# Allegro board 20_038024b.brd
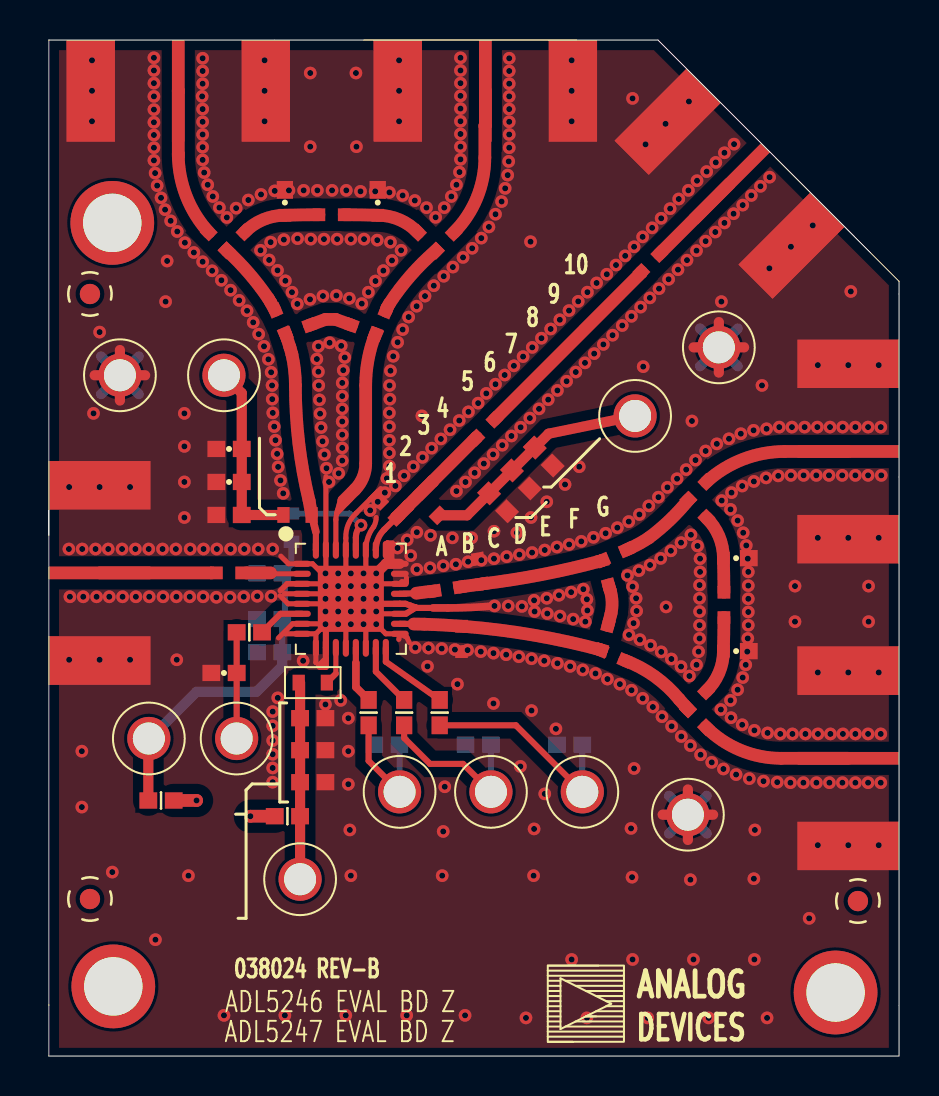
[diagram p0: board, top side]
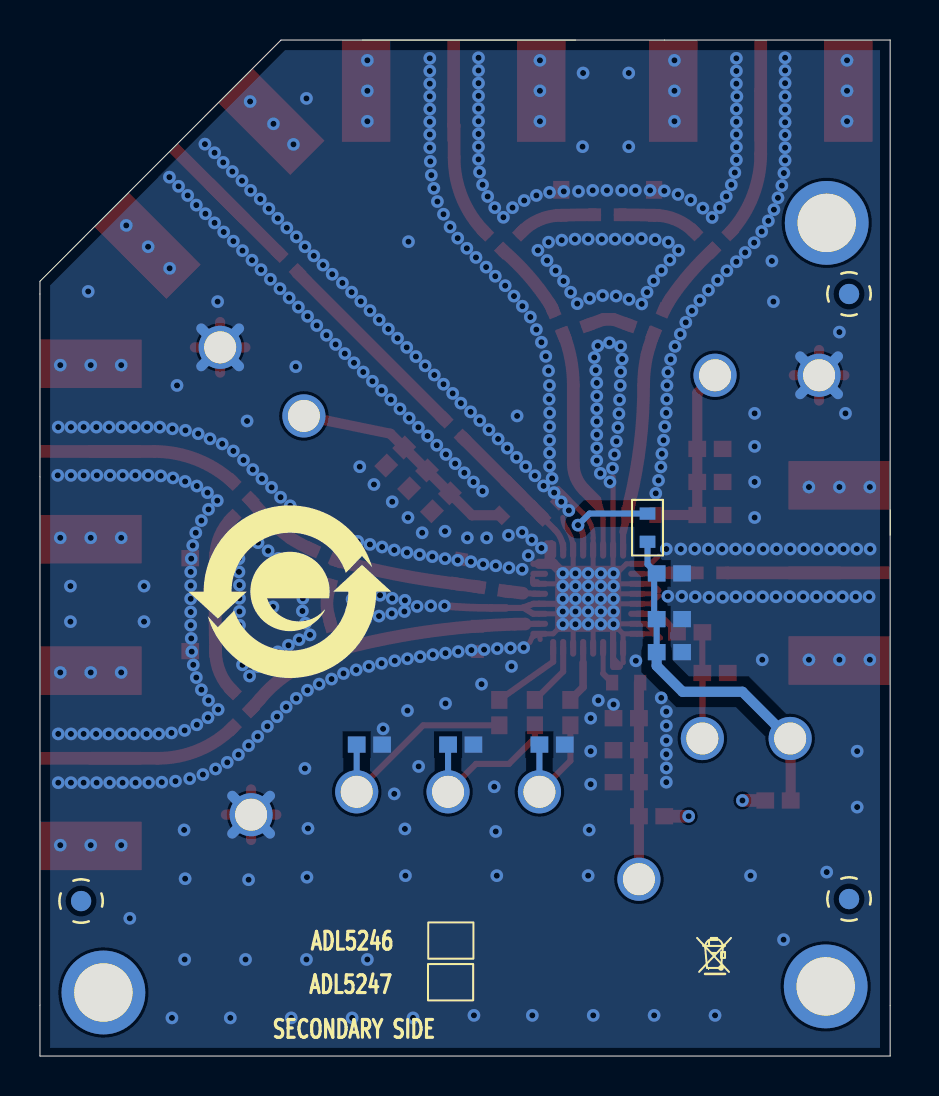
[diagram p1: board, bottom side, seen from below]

Outline 42.55 x 50.8 mm; copper layers: TOP, L2_GND, L3_VCC, BOTTOM. Coordinates in mm from the lower left corner of the outline.
Outline path: 0,27.3 0,0 42.55,0 42.55,38.73 30.48,50.8 15.75,50.8 ; 0,26.04 0,50.8 26.42,50.8

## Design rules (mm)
nets with their own width: min track width 0.508; nets AGND

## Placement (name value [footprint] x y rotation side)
C1  2.7pF  [C0402]  16.94 27.36 135 top
C2  0.1UF  [C0402]  13.21 13.69 180 top
C3  1.5pF  [C0402]  19.93 23.35 8.9 top
C4  1000pF  [C0402]  13.21 15.29 0 top
C5  100pF  [C0402]  9.02 27.05 180 top
C6  100pF  [C0402]  8.76 19.15 180 top
C7  100pF  [C0402]  13.21 16.89 0 top
C8  100pF  [C0402]  9.02 24.16 0 top
C9  100pF  [C0402]  8.45 40.73 315 top
C10  100pF  [C0402]  9.34 40.73 45 top
C11  100pF  [C0402]  16.92 15.57 180 bottom
C12  100pF  [C0402]  18.92 40.72 315 top
C13  100pF  [C0402]  19.81 40.72 225 top
C14  100pF  [C0402]  21.49 15.57 180 bottom
C15  100pF  [C0402]  26.06 15.57 180 bottom
C16  100pF  [C0402]  11.05 24.13 180 bottom
C17  1000pF  [C0402]  11.05 21.84 180 bottom
C18  100pF  [C0402]  32.45 27.36 315 top
C19  100pF  [C0402]  32.44 17.78 225 top
C20  0.1UF  [C0402]  11.05 20.19 0 bottom
C21  100pF  [C0402]  32.45 28.25 225 top
C22  100pF  [C0402]  32.44 16.89 135 top
C23  100pF  [C0402]  30.1 39.65 225 top
C24  100pF  [C0402]  22.48 27.69 315 top
C25  1000pF  [C0402]  23.62 28.83 315 top
C26  0.1UF  [C0402]  24.77 29.97 135 top
C27  100pF  [C0402]  12.45 36.32 200 top
C28  100pF  [C0402]  15.75 36.32 160 top
C29  100pF  [C0402]  27.85 24.16 285 top
C30  100pF  [C0402]  27.82 20.91 255 top
C31  100pF  [C0402]  34.39 24.89 0 top
C32  100pF  [C0402]  34.39 20.24 0 top
C33  100pF  [C0402]  11.81 42.67 90 top
C34  100pF  [C0402]  16.46 42.67 90 top
C40  0.1UF  [C0402]  9.02 30.35 0 top
C41  1000pF  [C0402]  9.02 28.7 180 top
GND1  BLK  [CNLOOPTP]  3.56 34.04 0 top
GND2  BLK  [CNLOOPTP]  33.53 35.43 0 top
GND3  BLK  [CNLOOPTP]  31.98 12.06 0 top
L1  100nH  [L7144]  12.45 27.05 0 top
L2  10NH  [L7144]  13.21 18.67 0 top
L3  100nH  [L7144]  12.14 26.42 270 bottom
L4  100nH  [L7144]  19 27.53 315 top
L5  TBD0402  [L0402]  20.65 20.85 270 top
L6  1nH  [L0402]  21.59 24.23 280 top
L7  TBD0402  [L0402]  33.78 22.56 270 top
L8  TBD0402  [L0402]  14.15 42.06 0 top
NOREF  -  [unnamed]  40.49 7.75 0 top
NOREF#2  -  [#2]  144.15 241.3 0 top
NOREF#3  -  [#2]  0 50.8 0 top
NOREF#4  -  [#2]  -121.16 -134.37 0 top
NOREF#5  -  [#2]  -155.57 170.18 0 top
NOREF#6  -  [#2]  149.86 63.5 180 top
NOREF#7  -  [#2]  167.16 -14.48 0 top
NOREF#8  -  [#2]  41.53 0 90 top
NOREF#9  -  [unnamed]  2.06 7.85 0 top
NOREF#10  -  [#2]  39.37 3.18 0 top
NOREF#11  -  [#2]  -240.23 -69.11 0 top
NOREF#12  -  [#2]  -155.57 200.66 0 top
NOREF#13  -  [#2]  24.97 0.71 0 top
NOREF#14  -  [unnamed]  2.06 38.1 0 top
NOREF#15  -  [#2]  0 0 0 top
NOREF#16  -  [#2]  -292.74 -238.76 0 top
NOREF#17  -  [#2]  -47.37 68.58 0 top
NOREF#18  -  [#2]  0 50.8 0 top
NOREF#19  -  [#2]  39.37 3.18 0 top
NOREF#20  -  [#2]  -237.72 -119 0 top
NOREF#21  -  [#2]  42.55 0 90 top
NOREF#22  -  [#2]  149.86 -15.24 90 top
NOREF#23  -  [#2]  39.37 3.18 0 top
NOREF#24  -  [#2]  0 63.53 270 top
NOREF#25  -  [#2]  0 -15.24 0 top
NOREF#26  -  [unnamed]  2.06 38.1 180 bottom
NOREF#27  -  [unnamed]  3.18 41.66 180 bottom
NOREF#28  -  [unnamed]  2.06 7.85 180 bottom
NOREF#29  -  [unnamed]  40.49 7.75 180 bottom
NOREF#30  -  [unnamed]  39.37 3.18 180 bottom
NOREF#31  -  [#2]  30.04 23.22 180 bottom
NOREF#32  -  [#2]  8.76 5 180 bottom
NOREF#33  -  [unnamed]  3.23 3.48 180 bottom
R1  0  [R0402]  21.84 31.37 45 top
R2  100  [R0402]  10.03 21.18 0 top
R3  100  [R0402]  16 17.17 270 top
R4  100  [R0402]  17.78 17.17 270 top
R5  100  [R0402]  19.56 17.17 270 top
R6  0  [R0402]  11.94 11.99 0 top
R7  0  [R0402]  5.61 12.78 0 top
R8  0  [R0402]  11.57 36.7 113.5 top
R9  0  [R0402]  16.61 36.66 66.5 top
R10  0  [R0402]  28.31 25.05 23.5 top
R11  0  [R0402]  28.23 20.03 337 top
RFIN1  JOHNSON142-0701-851  [CNJOHNSON142-0701-851]  2.54 24.16 180 top
RFIN2  JOHNSON142-0701-851  [CNJOHNSON142-0701-851]  21.84 48.26 90 top
RFIN3  JOHNSON142-0701-851  [CNJOHNSON142-0701-851]  40 30.23 0 top
RFOUT1  JOHNSON142-0701-851  [CNJOHNSON142-0701-851]  6.48 48.26 90 top
RFOUT2  JOHNSON142-0701-851  [CNJOHNSON142-0701-851]  40 14.88 0 top
RFOUT3  JOHNSON142-0701-851  [CNJOHNSON142-0701-851]  34.06 43.61 45 top
U1  ADL5246ACPZN  [QFN32_5X5_PAD3_3X3_3]  15.11 22.86 270 top
VCC1  RED  [CNLOOPTP]  8.76 34.04 0 top
VCC2  RED  [CNLOOPTP]  29.34 32 0 top
VGAIN1  YEL  [CNLOOPTP]  22.12 13.21 0 top
VGAIN2  YEL  [CNLOOPTP]  26.7 13.21 0 top
VPOS1  RED  [CNLOOPTP]  12.57 8.84 0 top
VPOS2  RED  [CNLOOPTP]  5 15.88 0 top
VSW1  YEL  [CNLOOPTP]  17.55 13.21 0 top
VSW1_N  YEL  [CNLOOPTP]  9.4 15.88 0 top

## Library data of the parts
C1 = CAP: Tolerance: +/-0.25; User Part Number: UPN; alternate symbols: (C0402H22_ALT,C0201-2,C0402_A,C0402_ALT); part number: CAP_SM-2.7PF,50V,+/-0.25,E020549,C0402; tolerance: +/-0.25
C2 C20 C26 C40 = CAP: Tolerance: 10; User Part Number: UPN; alternate symbols: (C0402H22_ALT,C0201-2,C0402_A,C0402_ALT); part number: CAP_SM-0.1UF,16V,10,E007200,C0402; tolerance: 10
C3 = CAP: Tolerance: +/-0.25pF; User Part Number: UPN; alternate symbols: (C0402H22_ALT,C0201-2,C0402_A,C0402_ALT); part number: CAP_SM-1.5PF,50V,+/-0.25PF,E012549,C0402; tolerance: +/-0.25pF
C4 C17 C25 C41 = CAP: Tolerance: 5; User Part Number: UPN; alternate symbols: (C0402H22_ALT,C0201-2,C0402_A,C0402_ALT); part number: CAP_SM-1000PF,50V,5,E012419,C0402; tolerance: 5
C5-C7 C11 C14-C16 C18 C19 C21-C24 C27-C32 = CAP: Tolerance: 5; User Part Number: UPN; alternate symbols: (C0402H22_ALT,C0201-2,C0402_A,C0402_ALT); part number: CAP_SM-100PF,50V,5,E007896,C0402; tolerance: 5
C8-C10 C12 C13 C33 C34 = CAP: User Part Number: UPN; Tolerance: 5; alternate symbols: (C0402H22_ALT,C0201-2,C0402_A,C0402_ALT); part number: CAP_SM-100PF,50V,5,E007896,C0402; tolerance: 5
GND1-GND3 = CNTP1P: User Part Number: UPN; alternate symbols: (CNBANANA_ALT); part number: CNTP1P_TH-BLK,E000948,CNLOOPTP
L1 L3 L4 = IND: Tolerance: 2; User Part Number: UPN; alternate symbols: (L0402-2,L0603_ALT); part number: IND_SM-100NH,2,E006304,L7144; tolerance: 2
L2 = IND: Tolerance: 5; User Part Number: UPN; alternate symbols: (L0402-2,L0603_ALT); part number: IND_SM-10NH,5,E006370,L7144; tolerance: 5
L5 L7 L8 = IND: User Part Number: UPN; alternate symbols: (L0402-2,L0603_ALT); part number: IND_SM-TBD0402,TBD0402,E002418,L0402
L6 = IND: Tolerance: 5; User Part Number: UPN; alternate symbols: (L0402-2,L0603_ALT); part number: IND_SM-1NH,5,E007929,L0402; tolerance: 5
R1 R6 R7 R10 = RES: Tolerance: 5; User Part Number: UPN; alternate symbols: (RRAD984L1500W75H520LD32;TO220H590_ALT;R0402_A;R0603_A); part number: RES_SM-0,E003438,1/16W,5,PANASONIC,ERJ-2GE0R00X,SCD-002744,R0402,N/A; tolerance: 5
R2-R5 = RES: Tolerance: 1; User Part Number: UPN; alternate symbols: (RRAD984L1500W75H520LD32;TO220H590_ALT;R0402_A;R0603_A); part number: RES_SM-100,E016329,1/10W,1,PANASONIC,ERJ-2RKF1000X,SCD-001006,R0402,N/A; tolerance: 1
R8 R9 R11 = RES: User Part Number: UPN; Tolerance: 5; alternate symbols: (RRAD984L1500W75H520LD32;TO220H590_ALT;R0402_A;R0603_A); part number: RES_SM-0,E003438,1/16W,5,PANASONIC,ERJ-2GE0R00X,SCD-002744,R0402,N/A; tolerance: 5
RFIN1-RFIN3 RFOUT1-RFOUT3 = CNBNC5P: User Part Number: UPN; alternate symbols: (CNAMPHENOL132255-11_ALT); part number: CNBNC5P_SM-JOHNSON142-0701-851,E000923,JOHNSON,142-0701-851,SCD-010536,CNJOHNSON142-0701-851
U1 = ADL5246: User Part Number: UPN; part number: ADL5246_SM-ADL5246ACPZN,E018031,ADI,ADL5246ACPZN,HTTP://WWMFG.ANALOG.COM/WWMFG/APPS/HLM/ATTACHMENT/VIEW/232495,QFN32_5X5_PAD3_3X3_3,N/A
VCC1 VCC2 VPOS1 VPOS2 = CNTP1P: User Part Number: UPN; alternate symbols: (CNBANANA_ALT); part number: CNTP1P_TH-RED,E000947,CNLOOPTP
VGAIN1 VGAIN2 VSW1 VSW1_N = CNTP1P: User Part Number: UPN; alternate symbols: (CNBANANA_ALT); part number: CNTP1P_TH-YEL,E000945,CNLOOPTP

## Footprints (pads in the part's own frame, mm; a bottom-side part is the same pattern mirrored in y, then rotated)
C0402
  rect 0.635x0.635 smd: 1(-0.635,0) 2(0.635,0)
CNJOHNSON142-0701-851
  rect 5.08x0.635 smd: 1(0,0)
  rect 5.08x2.413 smd: 2(0,4.381) 3(0,4.381) 4(0,-4.381) 5(0,-4.381)
CNLOOPTP
  round 2.159 hole 1.6: 1(0,0)
L0402
  rect 0.635x0.635 smd: 1(-0.635,0) 2(0.635,0)
L7144
  rect 0.61x0.787 smd: 1(-0.705,0) 2(0.705,0)
QFN32_5X5_PAD3_3X3_3
  oval 0.305x0.889 smd: 1(-1.75,-2.45) 2(-1.25,-2.45) 3(-0.75,-2.45) 4(-0.25,-2.45) 5(0.25,-2.45) 6(0.75,-2.45) 7(1.25,-2.45) 8(1.75,-2.45) 17(1.75,2.45) 18(1.25,2.45) 19(0.75,2.45) 20(0.25,2.45) 21(-0.25,2.45) 22(-0.75,2.45) 23(-1.25,2.45) 24(-1.75,2.45)
  oval 0.889x0.305 smd: 9(2.45,-1.75) 10(2.45,-1.25) 11(2.45,-0.75) 12(2.45,-0.25) 13(2.45,0.25) 14(2.45,0.75) 15(2.45,1.25) 16(2.45,1.75) 25(-2.45,1.75) 26(-2.45,1.25) 27(-2.45,0.75) 28(-2.45,0.25) 29(-2.45,-0.25) 30(-2.45,-0.75) 31(-2.45,-1.25) 32(-2.45,-1.75)
  rect 3.302x3.302 smd: PAD(0,0)
R0402
  rect 0.635x0.635 smd: 1(-0.635,0) 2(0.635,0)
unnamed
  round 1.016 smd: (0,0)

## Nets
AGND: C1.2(N2) C2.1(N1) C4.2(N2) C5.2(N2) C6.2(N2) C7.2(N2) C11.2(N2) C14.2(N2) C15.2(N2) C16.2(N2) C17.2(N2) C20.1(N1) C24.2(N2) C25.2(N2) C26.1(N1) C31.2(N2) C32.2(N2) C33.2(N2) C34.2(N2) C40.1(N1) C41.2(N2) GND1.1(N1) GND2.1(N1) GND3.1(N1) L5.2(N2) L6.1(N1) RFIN1.2(SH1) RFIN1.3(SH2) RFIN1.4(SH3) RFIN1.5(SH4) RFIN2.2(SH1) RFIN2.3(SH2) RFIN2.4(SH3) RFIN2.5(SH4) RFIN3.2(SH1) RFIN3.3(SH2) RFIN3.4(SH3) RFIN3.5(SH4) RFOUT1.2(SH1) RFOUT1.3(SH2) RFOUT1.4(SH3) RFOUT1.5(SH4) RFOUT2.2(SH1) RFOUT2.3(SH2) RFOUT2.4(SH3) RFOUT2.5(SH4) RFOUT3.2(SH1) RFOUT3.3(SH2) RFOUT3.4(SH3) RFOUT3.5(SH4) U1.1(GND1) U1.3(GND2) U1.4(GND3) U1.5(GND4) U1.7(GND5) U1.8(GND6) U1.9(GND7) U1.10(GND8) U1.12(GND9) U1.14(GND10) U1.17(GND11) U1.19(GND12) U1.20(GND13) U1.22(GND14) U1.23(GND15) U1.24(GND16) U1.25(GND17) U1.27(GND18) U1.29(GND19) U1.31(GND20) U1.PAD(EP)
VCC1: C5.1(N1) C40.2(N2) C41.1(N1) L1.1(N1) VCC1.1(N1)
VCC2: C24.1(N1) C25.1(N1) C26.2(N2) L4.2(N2) VCC2.1(N1)
RFIN1: C8.1(N1) RFIN1.1(CNTR)
UNNAMED_4_ADL5246_I245_RFIN1: C8.2(N2) U1.2(RFIN1)
UNNAMED_4_ADL5246_I245_RFOUT3: C1.1(N1) L4.1(N1) R1.1(N1) U1.26(RFOUT3)
UNNAMED_4_ADL5246_I245_VGAIN1: R4.1(N1) U1.15(VGAIN1)
UNNAMED_4_ADL5246_I245_VGAIN2: R5.1(N1) U1.16(VGAIN2)
UNNAMED_4_ADL5246_I245_VPOS1: L2.2(N2) U1.11(VPOS1)
UNNAMED_4_ADL5246_I245_VPOS2: L3.1(N1) U1.28(VPOS2)
UNNAMED_4_ADL5246_I245_VSW1: R3.1(N1) U1.13(VSW1)
UNNAMED_4_ADL5246_I245_VSW1N: R2.2(N2) U1.6(VSW1_N)
UNNAMED_4_CAP_I120_N1: C10.2(N2) C33.1(N1) L8.1(N1)
UNNAMED_4_CAP_I120_N2: C9.2(N2) C10.1(N1) R8.2(N2)
UNNAMED_4_CAP_I122_N1: C12.2(N2) C13.2(N2) R9.2(N2)
UNNAMED_4_CAP_I122_N2: C12.1(N1) C34.1(N1) L8.2(N2)
UNNAMED_4_CAP_I124_N1: C18.1(N1) C21.2(N2) R10.2(N2)
UNNAMED_4_CAP_I124_N2: C18.2(N2) C31.1(N1) L7.1(N1)
UNNAMED_4_CAP_I125_N1: C19.1(N1) C32.1(N1) L7.2(N2)
UNNAMED_4_CAP_I125_N2: C19.2(N2) C22.2(N2) R11.2(N2)
UNNAMED_4_CAP_I127_N1: C22.1(N1) RFOUT2.1(CNTR)
UNNAMED_4_CAP_I131_N1: C21.1(N1) RFIN3.1(CNTR)
UNNAMED_4_CAP_I145_N1: C23.1(N1) RFOUT3.1(CNTR)
UNNAMED_4_CAP_I145_N2: C23.2(N2) R1.2(N2)
UNNAMED_4_CAP_I154_N1: C9.1(N1) RFOUT1.1(CNTR)
UNNAMED_4_CAP_I155_N1: C13.1(N1) RFIN2.1(CNTR)
UNNAMED_4_CAP_I166_N1: C27.1(N1) C28.2(N2)
UNNAMED_4_CAP_I166_N2: C27.2(N2) L1.2(N2) R8.1(N1) U1.32(RFOUT1)
UNNAMED_4_CAP_I167_N1: C28.1(N1) R9.1(N1) U1.30(RFIN2)
UNNAMED_4_CAP_I168_N1: C29.2(N2) C30.1(N1)
UNNAMED_4_CAP_I168_N2: C30.2(N2) L5.1(N1) R11.1(N1) U1.18(RFOUT2)
UNNAMED_4_CAP_I169_N1: C3.2(N2) C29.1(N1) L6.2(N2) R10.1(N1)
UNNAMED_4_CAP_I221_N1: C3.1(N1) U1.21(RFIN3)
UNNAMED_4_CAP_I233_N1: C6.1(N1) R2.1(N1) VSW1_N.1(N1)
UNNAMED_4_CAP_I235_N1: C11.1(N1) R3.2(N2) VSW1.1(N1)
UNNAMED_4_CAP_I236_N1: C14.1(N1) R4.2(N2) VGAIN1.1(N1)
UNNAMED_4_CAP_I237_N1: C15.1(N1) R5.2(N2) VGAIN2.1(N1)
VPOS: R6.1(N1) R7.2(N2)
VPOS1: C2.2(N2) C4.1(N1) C7.1(N1) L2.1(N1) R6.2(N2) VPOS1.1(N1)
VPOS2: C16.1(N1) C17.1(N1) C20.2(N2) L3.2(N2) R7.1(N1) VPOS2.1(N1)

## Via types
v1: diameter 0.635, hole 0.305, TOP to BOTTOM, 594 vias

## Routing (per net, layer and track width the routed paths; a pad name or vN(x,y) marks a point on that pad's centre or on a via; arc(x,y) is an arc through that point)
AGND: length 123.1
  TOP w0.254: v1(14.48,23.5) 14.36,23.61 12.67,23.61 ; 16.61,28.37 15.38,27.14 arc(14.98,26.57) 14.86,25.9 U1.29 14.86,23.11 ; 16.94,25.65 16.86,25.58 U1.25 ; 16.94,25.65 17.04,25.55 17.04,25.13 ; 16.94,25.65 17.2,25.65 ; 11.8,23.11 11.8,23.11 U1.4 14.86,23.11 ; U1.14 15.86,22.11 ; 15.86,22.11 v1(16.38,21.59) 16.86,21.11 U1.17 ; 15.86,22.11 v1(15.75,22.22) ; 15.86,22.11 U1.19 17.87,22.11 ; U1.17 17.92,20.93 18.03,20.68 ; U1.17 17.51,20.83 ; 11.61,24.99 11.99,24.61 U1.1 13.2,24.61 13.68,24.13 v1(13.84,24.13) ; 13.36,21.11 U1.9 13.36,19.67 13.36,19.67 ; 13.36,21.11 v1(13.84,21.59) ; 13.36,21.11 U1.8 11.85,21.11 11.85,21.11 ; 14.86,22.61 U1.5 11.97,22.61 11.57,23.01 ; 14.86,22.61 v1(15.11,22.86) ; 14.86,22.61 U1.12 ; 15.86,25.31 15.86,23.61 ; 15.86,25.31 U1.27 ; 15.86,25.31 arc(15.96,25.92) 16.26,26.47 arc(16.35,26.69) 16.38,26.92 ; 15.86,23.61 U1.22 ; 15.86,23.61 v1(15.75,23.5) v1(15.11,22.86) ; 13.86,24.11 U1.31 13.86,28.96 ; U1.22 17.66,23.71 17.89,23.71 ; U1.22 17.79,23.61 17.89,23.71 ; 14.86,23.11 v1(15.11,22.86) ; v1(13.84,21.59) 13.86,21.57 ; v1(13.84,21.59) 13.86,21.61 ; 17.89,23.71 17.89,23.91 ; 13.86,19.45 13.84,19.43 13.54,19.43 ; 13.86,21.61 v1(14.48,22.22) ; 13.86,21.61 U1.7 12.2,21.61 11.49,20.9
  TOP w0.279: 12.67,23.61 U1.3 11.93,23.61 11.58,23.27
  TOP w0.305: 18.36,22.43 18.22,22.34 17.87,22.11 ; 18.36,22.43 18.07,22.53 17.86,22.61 17.56,22.61 ; 18.36,22.43 18.36,22.4 19.23,22.4 ; 17.56,22.61 U1.20 ; 17.56,22.61 15.36,22.61 v1(15.11,22.86) ; 13.86,19.45 13.86,19.86 ; 13.86,19.86 U1.10 13.86,21.57 ; 13.86,19.86 13.51,19.51
  TOP w0.381: 19.23,22.4 19.96,22.4 arc(21.13,22.43) v1(22.3,22.5)
  TOP w0.508: 33.53,34.17 GND2.1 ; GND2.1 33.53,36.7 ; GND2.1 32.27,35.43 ; GND2.1 34.79,35.43 ; 2.29,34.04 GND1.1 ; GND1.1 3.56,35.3 ; GND1.1 4.82,34.04 ; GND1.1 3.56,32.77 ; L5.2 20.78,20.29 ; 16.86,24.61 v1(16.38,24.13) ; 16.86,24.61 U1.24 ; 16.86,24.61 17.04,24.79 17.04,25.13 ; GND3.1 33.24,12.06 ; GND3.1 30.72,12.06 ; GND3.1 31.98,10.8 ; GND3.1 31.98,13.33 ; C1.2 16.46,27.64
  L2_GND w0.508: 30.72,12.06 GND3.1 ; GND3.1 31.98,10.8 ; GND3.1 31.98,13.33 ; GND3.1 33.24,12.06 ; 32.27,35.43 GND2.1 ; GND2.1 34.79,35.43 ; GND2.1 33.53,36.7 ; GND2.1 33.53,34.17 ; 2.29,34.04 GND1.1 ; GND1.1 3.56,32.77 ; GND1.1 4.82,34.04 ; GND1.1 3.56,35.3
  L3_VCC w0.508: 30.72,12.06 GND3.1 ; GND3.1 33.24,12.06 ; GND3.1 31.98,13.33 ; GND3.1 31.98,10.8 ; 3.56,32.77 GND1.1 ; GND1.1 4.82,34.04 ; GND1.1 3.56,35.3 ; GND1.1 2.29,34.04 ; 32.27,35.43 GND2.1 ; GND2.1 33.53,36.7 ; GND2.1 34.79,35.43 ; GND2.1 33.53,34.17
  BOTTOM w0.508: GND2.1 34.47,34.49 ; GND2.1 34.47,36.38 ; GND2.1 32.58,36.38 ; GND2.1 32.58,34.49 ; 31.03,13.01 GND3.1 ; GND3.1 32.92,11.12 ; GND3.1 31.03,11.12 ; GND3.1 32.92,13.01 ; GND1.1 4.5,34.98 ; GND1.1 2.61,33.09 ; GND1.1 2.61,34.98 ; GND1.1 4.5,33.09
  vias: v1(1.02,28.45) v1(1,25.35) v1(1.05,22.96) v1(1.02,19.81) v1(1.67,25.35) v1(1.65,15.24) v1(1.65,12.45) v1(1.72,22.96) v1(2.16,49.78) v1(2.16,48.26) v1(2.16,46.74) v1(2.24,32.13) v1(2.34,25.35) v1(2.39,22.96) v1(2.54,36.2) v1(2.54,28.45) v1(2.54,19.81) v1(2.97,25.35) v1(3.02,22.96) v1(3.18,9.19) v1(3.66,25.35) v1(3.69,22.96) v1(4.06,28.45) v1(4.06,19.81) v1(4.33,25.35) v1(4.36,22.96) v1(5,25.35) v1(5.02,22.96) v1(5.26,49.91) v1(5.26,49.28) v1(5.26,48.64) v1(5.26,47.98) v1(5.26,47.32) v1(5.26,46.68) v1(5.26,46.05) v1(5.26,45.42) v1(5.26,44.78) v1(5.32,44.15) v1(5.33,5.82) v1(5.42,43.52) v1(5.61,42.91) v1(5.69,25.35) v1(5.71,22.96) v1(5.82,42.32) v1(5.84,37.72) v1(5.92,39.75) v1(6.1,41.76) v1(6.36,25.35) v1(6.43,41.22) v1(6.38,22.96) v1(6.4,19.81) v1(6.81,40.67) v1(6.78,32.13) v1(6.78,30.48) v1(6.78,28.7) v1(6.78,26.92) v1(7.07,25.35) v1(7.05,22.96) v1(6.99,9.02) v1(7.26,40.17) v1(7.67,47.98) v1(7.7,49.89) v1(7.7,49.25) v1(7.7,48.62) v1(7.7,47.35) v1(7.7,46.71) v1(7.7,46.08) v1(7.7,45.44) v1(7.7,44.81) v1(7.77,44.17) v1(7.7,39.71) v1(7.74,25.35) v1(7.72,22.96) v1(7.95,43.56) v1(8.17,39.26) v1(8.2,42.98) v1(8.41,25.35) v1(8.38,22.94) v1(8.53,42.42) v1(8.64,38.79) v1(8.76,2.03) v1(8.91,41.93) v1(9.07,22.94) v1(9.09,38.29) v1(9.09,25.35) v1(9.37,42.39) v1(9.52,37.78) v1(9.75,22.96) v1(9.78,25.35) v1(9.92,37.26) v1(9.98,42.8) v1(10.23,36.68) v1(10.43,22.99) v1(10.5,36.09) v1(10.48,25.35) v1(10.62,43.08) v1(10.59,40.28) v1(10.77,35.48) v1(10.79,49.78) v1(10.79,48.26) v1(10.79,46.74) v1(11.02,39.8) v1(10.99,34.83) v1(11.1,40.69) v1(11.12,34.19) v1(11.17,33.53) v1(11.13,22.99) v1(11.18,32.84) v1(11.21,32.16) v1(11.2,25.35) v1(11.2,17.22) v1(11.2,16.51) v1(11.2,15.77) v1(11.2,15.09) v1(11.2,14.4) v1(11.2,13.69) v1(11.3,43.26) v1(11.28,31.47) v1(11.34,30.79) v1(11.44,39.28) v1(11.42,30.11) v1(11.47,29.45) v1(11.46,17.91) v1(11.59,28.78) v1(11.76,40.82) v1(11.73,28.13) v1(11.84,38.76) v1(11.81,2.03) v1(12.01,43.28) v1(12.17,38.19) v1(12.45,40.87) v1(12.43,37.6) v1(12.75,43.28) v1(12.73,19.76) v1(13.07,37.83) v1(13.08,49.15) v1(13.08,45.47) v1(13.11,40.84) v1(13.44,43.28) v1(13.41,34.85) v1(13.49,35.48) v1(13.49,34.21) v1(13.51,33.53) v1(13.54,32.81) v1(13.57,32.12) v1(13.62,31.42) v1(13.77,40.84) v1(13.72,38) v1(13.7,30.73) v1(13.79,30.07) v1(13.84,23.5) v1(13.84,22.86) v1(13.84,22.22) v1(13.84,17.58) v1(13.89,29.39) v1(14.05,35.66) v1(14.02,28.7) v1(14.17,43.28) v1(14.43,40.84) v1(14.39,38.02) v1(14.5,29.13) v1(14.48,24.13) v1(14.48,22.86) v1(14.48,21.59) v1(14.63,35.51) v1(14.61,17.78) v1(14.73,34.29) v1(14.68,33.66) v1(14.68,32.99) v1(14.68,32.36) v1(14.68,31.72) v1(14.68,31.06) v1(14.68,30.4) v1(14.68,29.77) v1(14.81,34.92) v1(14.86,2.03) v1(14.88,43.28) v1(15.04,37.88) v1(14.99,16.89) v1(14.99,15.24) v1(14.99,13.59) v1(15.06,11.3) v1(15.11,40.84) v1(15.11,24.13) v1(15.11,23.5) v1(15.11,22.22) v1(15.11,21.59) v1(15.11,9.02) v1(15.37,49.15) v1(15.39,45.47) v1(15.6,43.23) v1(15.66,37.62) v1(15.77,40.84) v1(15.75,24.13) v1(15.75,22.86) v1(15.75,21.59) v1(15.99,38.19) v1(16.08,27.28) v1(16.33,43.23) v1(16.34,38.75) v1(16.43,40.79) v1(16.46,27.71) v1(16.38,23.5) v1(16.38,22.86) v1(16.38,22.22) v1(16.74,39.27) v1(16.81,28.17) v1(16.92,28.88) v1(17.04,43.18) v1(17.05,33.53) v1(17.07,32.84) v1(17.04,32.16) v1(17.04,31.47) v1(17.04,30.78) v1(17.04,30.15) v1(17.04,29.49) v1(17.09,40.69) v1(17.17,39.78) v1(17.1,34.26) v1(17.23,34.99) v1(17.34,28.5) v1(17.45,35.69) v1(17.45,25.4) v1(17.53,49.78) v1(17.53,48.26) v1(17.53,46.74) v1(17.63,40.28) v1(17.7,43.03) v1(17.71,36.32) v1(17.78,29.01) v1(17.93,25.81) v1(17.91,2.03) v1(18.01,36.95) v1(18.11,25.02) v1(18.24,29.47) v1(18.31,42.77) v1(18.34,20.42) v1(18.4,37.49) v1(18.42,26.19) v1(18.42,24.33) v1(18.67,32) v1(18.7,29.93) v1(18.82,37.99) v1(18.9,42.42) v1(18.95,19.48) v1(19,20.4) v1(19.16,30.39) v1(19.1,26.04) v1(19.08,24.41) v1(19.26,38.52) v1(19.35,41.94) v1(19.62,30.85) v1(19.66,20.37) v1(19.76,38.99) v1(19.74,24.51) v1(19.74,11.23) v1(19.68,9.02) v1(19.79,42.42) v1(19.81,13.46) v1(20.14,42.98) v1(20.08,31.31) v1(20.22,39.45) v1(20.19,25.91) v1(20.37,24.59) v1(20.32,20.32) v1(20.4,43.56) v1(20.4,28.24) v1(20.45,18.59) v1(20.55,44.2) v1(20.54,31.77) v1(20.6,49.91) v1(20.6,49.28) v1(20.6,48.64) v1(20.6,48.01) v1(20.6,47.37) v1(20.6,46.74) v1(20.6,46.1) v1(20.6,45.47) v1(20.6,44.83) v1(20.73,39.93) v1(20.85,28.7) v1(20.83,2.03) v1(20.96,20.29) v1(21,32.21) v1(20.98,24.71) v1(21.16,25.91) v1(21.18,40.39) v1(21.31,29.16) v1(21.48,32.64) v1(21.64,40.89) v1(21.64,24.79) v1(21.62,20.22) v1(21.77,29.62) v1(21.89,33.13) v1(22.02,41.45) v1(22.23,30.08) v1(22.25,20.14) v1(22.25,17.63) v1(22.35,42.09) v1(22.35,33.59) v1(22.28,26.24) v1(22.28,24.87) v1(22.66,42.72) v1(22.69,30.54) v1(22.83,43.38) v1(22.81,34.05) v1(22.96,44.04) v1(22.91,24.97) v1(22.89,20.07) v1(23.04,49.89) v1(23.04,49.25) v1(23.04,48.62) v1(23.04,47.98) v1(23.04,47.35) v1(23.04,46.71) v1(23.04,46.08) v1(23.04,45.42) v1(23.01,44.73) v1(22.99,22.5) v1(23.15,31) v1(23.27,34.51) v1(23.42,26.16) v1(23.55,25.07) v1(23.52,19.96) v1(23.61,31.44) v1(23.67,22.48) v1(23.6,14.48) v1(23.73,34.97) v1(23.88,1.91) v1(24.07,31.9) v1(24.1,40.72) v1(24.13,26.92) v1(24.16,19.86) v1(24.16,17.27) v1(24.19,35.43) v1(24.18,25.17) v1(24.26,9.02) v1(24.28,22.78) v1(24.31,22.22) v1(24.28,11.35) v1(24.53,32.36) v1(24.65,35.89) v1(24.82,25.3) v1(24.79,19.76) v1(24.82,13.11) v1(24.92,27.71) v1(24.92,22.89) v1(24.94,22.12) v1(24.99,32.82) v1(25.11,36.35) v1(25.37,16.36) v1(25.45,33.28) v1(25.43,25.45) v1(25.45,19.63) v1(25.57,36.81) v1(25.53,23.04) v1(25.58,22) v1(25.83,28.57) v1(25.91,33.74) v1(26.03,37.27) v1(26.04,25.58) v1(26.16,49.78) v1(26.16,48.26) v1(26.16,46.74) v1(26.14,23.19) v1(26.09,19.48) v1(26.16,4.83) v1(26.24,21.84) v1(26.37,34.2) v1(26.49,37.73) v1(26.54,29.46) v1(26.64,25.73) v1(26.75,23.34) v1(26.72,19.3) v1(26.83,34.66) v1(26.85,21.72) v1(26.95,38.19) v1(26.92,22.83) v1(26.95,22.28) v1(26.92,1.91) v1(27.25,25.93) v1(27.29,35.12) v1(27.36,19.13) v1(27.41,38.65) v1(27.75,35.58) v1(27.86,26.14) v1(27.92,39.09) v1(27.95,18.85) v1(28.21,36.04) v1(28.38,39.55) v1(28.45,26.42) v1(28.57,18.59) v1(28.69,36.53) v1(28.84,40.01) v1(28.96,24.03) v1(29.02,26.72) v1(29.03,21.06) v1(29.15,36.99) v1(29.16,18.29) v1(29.13,11.38) v1(29.21,47.88) v1(29.21,23.47) v1(29.26,21.64) v1(29.18,8.94) v1(29.21,4.83) v1(29.29,40.46) v1(29.29,14.38) v1(29.39,22.89) v1(29.41,22.25) v1(29.55,27.08) v1(29.53,24.27) v1(29.61,37.45) v1(29.58,20.82) v1(29.71,40.96) v1(29.74,34.47) v1(29.72,17.88) v1(29.86,45.58) v1(29.97,1.91) v1(30.07,37.91) v1(30.02,27.51) v1(30.09,24.55) v1(30.11,20.54) v1(30.19,41.41) v1(30.23,17.45) v1(30.53,38.37) v1(30.51,27.94) v1(30.64,41.88) v1(30.62,24.88) v1(30.65,20.21) v1(30.68,16.97) v1(30.86,46.61) v1(30.95,28.43) v1(30.89,22.45) v1(31.01,38.84) v1(31.09,42.37) v1(31.13,25.26) v1(31.15,19.85) v1(31.17,16.48) v1(31.44,28.86) v1(31.52,42.85) v1(31.48,39.32) v1(31.64,25.67) v1(31.64,19.47) v1(31.65,15.98) v1(31.93,39.79) v1(31.89,29.32) v1(32.03,47.73) v1(32,43.28) v1(32.05,19) v1(32.13,26.06) v1(32.11,15.52) v1(32.11,8.81) v1(32.18,31.75) v1(32.26,4.83) v1(32.36,29.79) v1(32.44,43.76) v1(32.41,40.27) v1(32.46,25.5) v1(32.41,19.56) v1(32.56,23.55) v1(32.56,22.89) v1(32.56,22.22) v1(32.56,21.54) v1(32.56,20.88) v1(32.51,20.22) v1(32.59,24.87) v1(32.59,24.21) v1(32.61,15.06) v1(32.87,40.74) v1(32.87,30.25) v1(32.92,44.22) v1(33.02,1.91) v1(33.17,14.68) v1(33.35,41.2) v1(33.38,44.68) v1(33.43,30.61) v1(33.66,37.72) v1(33.67,27.77) v1(33.63,17.32) v1(33.76,14.35) v1(33.81,45.16) v1(33.81,41.66) v1(34.04,30.86) v1(34.16,28.17) v1(34.11,27.33) v1(34.11,17.78) v1(34.14,16.92) v1(34.26,42.11) v1(34.29,45.59) v1(34.47,26.77) v1(34.47,18.31) v1(34.39,14.07) v1(34.63,31.11) v1(34.72,42.55) v1(34.7,28.5) v1(34.75,26.16) v1(34.72,18.92) v1(34.7,16.56) v1(34.87,19.56) v1(34.9,25.53) v1(34.95,20.22) v1(34.98,24.87) v1(35,24.21) v1(35,23.52) v1(35,22.86) v1(35,22.2) v1(35,21.54) v1(34.98,20.88) v1(35.05,13.87) v1(35.15,43.03) v1(35.26,31.28) v1(35.28,28.73) v1(35.31,16.28) v1(35.33,11.3) v1(35.28,8.86) v1(35.31,4.83) v1(35.61,43.48) v1(35.69,33.53) v1(35.76,13.74) v1(35.92,31.36) v1(35.89,28.91) v1(35.97,16.15) v1(35.94,1.91) v1(36.07,43.94) v1(36.06,39.38) v1(36.45,13.69) v1(36.55,31.45) v1(36.5,29.01) v1(36.6,16.1) v1(37.13,40.46) v1(37.13,29.03) v1(37.11,13.67) v1(37.19,31.45) v1(37.21,16.1) v1(37.34,23.5) v1(37.34,21.72) v1(37.77,29.03) v1(37.76,13.67) v1(37.82,31.45) v1(37.86,16.1) v1(38.05,6.88) v1(38.23,41.53) v1(38.46,31.45) v1(38.4,29.03) v1(38.41,13.67) v1(38.48,34.54) v1(38.48,25.91) v1(38.48,19.18) v1(38.49,16.1) v1(38.48,10.54) v1(39.04,29.03) v1(39.06,13.67) v1(39.09,31.45) v1(39.11,16.1) v1(39.73,31.45) v1(39.7,29.03) v1(39.74,16.1) v1(39.71,13.67) v1(40,34.54) v1(40,25.91) v1(40,19.18) v1(40,10.54) v1(40.13,38.23) v1(40.36,31.45) v1(40.36,29.03) v1(40.36,16.1) v1(40.36,13.67) v1(41,31.45) v1(41,29.03) v1(41.02,23.5) v1(41.02,21.72) v1(41,16.1) v1(41,13.67) v1(41.53,34.54) v1(41.53,25.91) v1(41.53,19.18) v1(41.53,10.54) v1(41.63,31.45) v1(41.66,29.03) v1(41.63,16.1) v1(41.63,13.67)
VCC1: length 9.4
  TOP w0.508: VCC1.1 9.65,33.15 C40.2 C41.1 C5.1 L1.1
VCC2: length 11.6
  TOP w0.508: L4.2 20.93,27.04 C24.1 C25.1 C26.2 25.01,31.12 VCC2.1
RFIN1: length 5.8
  TOP w0.203: C8.1 8.17,24.16
  TOP w0.635: 8.17,24.16 RFIN1.1
UNNAMED_4_ADL5246_I245_RFIN1: length 3
  TOP w0.203: 9.87,24.16 C8.2
  TOP w0.254: 11.1,24.16 11.15,24.11 U1.2 12.67,24.11
  TOP w0.635: 11.1,24.16 9.87,24.16
UNNAMED_4_ADL5246_I245_RFOUT3: length 9.5
  TOP w0.254: 17.39,26.92 17.4,26.92
  TOP w0.305: U1.26 16.36,25.31 arc(16.47,25.85) 16.78,26.31 17.39,26.93 ; 21.39,30.92 R1.1
  TOP w0.635: 17.98,27.51 17.98,27.5 17.4,26.92 ; 17.98,27.51 19.21,28.74 ; 17.98,27.51 17.97,27.5 17.39,26.93 C1.1 ; 21.39,30.92 21.39,30.92 19.21,28.74 ; 19.21,28.74 19.21,28.74 L4.1
UNNAMED_4_ADL5246_I245_VGAIN1: length 3.2
  TOP w0.254: 16.36,20.41 U1.15
  TOP w0.305: R4.1 16.36,19.22 U1.15
UNNAMED_4_ADL5246_I245_VGAIN2: length 4
  TOP w0.254: 16.86,20.41 U1.16
  TOP w0.305: R5.1 16.86,19.71 U1.16
UNNAMED_4_ADL5246_I245_VPOS1: length 1.9
  TOP w0.254: 14.36,19.12 U1.11 14.36,20.41
  TOP w0.305: 14.36,19.12 L2.2
UNNAMED_4_ADL5246_I245_VPOS2: length 5
  TOP w0.254: 15.36,25.31 U1.28
  TOP w0.305: U1.28 15.36,25.92 arc(15.43,26.26) v1(15.62,26.54)
  BOTTOM w0.305: v1(15.62,26.54) 15.04,27.12 L3.1
UNNAMED_4_ADL5246_I245_VSW1: length 2.9
  TOP w0.305: U1.13 15.36,19.66 15.37,19.66
  TOP w0.381: R3.1 15.37,18.44 15.37,19.66
UNNAMED_4_ADL5246_I245_VSW1N: length 2.4
  TOP w0.254: 12.67,22.11 U1.6
  TOP w0.305: U1.6 11.59,22.11 10.67,21.18
UNNAMED_4_CAP_I120_N1: length 4
  TOP w0.635: C10.2 arc(10.71,41.81) C33.1 arc(12.66,42.06) L8.1
UNNAMED_4_CAP_I120_N2: length 3.9
  TOP w0.635: R8.2 11.1,37.68 10.99,37.87 arc(10.01,39.14) C9.2
UNNAMED_4_CAP_I122_N1: length 3.9
  TOP w0.635: R9.2 16.88,37.27 16.92,37.4 17.04,37.62 arc(18.11,39.03) C13.2
UNNAMED_4_CAP_I122_N2: length 3.9
  TOP w0.635: C12.1 arc(17.56,41.81) C34.1 arc(15.62,42.06) L8.2
UNNAMED_4_CAP_I124_N1: length 4
  TOP w0.635: R10.2 29.16,25.43 arc(29.6,25.65) 30.02,25.91 arc(31.07,26.79) C21.2
UNNAMED_4_CAP_I124_N2: length 4
  TOP w0.635: L7.1 arc(33.78,24.04) C31.1 arc(33.53,25.99) C18.2
UNNAMED_4_CAP_I125_N1: length 3.9
  TOP w0.635: L7.2 arc(33.78,21.08) C32.1 arc(33.53,19.15) C19.1
UNNAMED_4_CAP_I125_N2: length 4.1
  TOP w0.635: C19.2 31.55,17.83 arc(30.31,18.99) R11.2
UNNAMED_4_CAP_I127_N1: length 7.5
  TOP w0.635: RFOUT2.1 36.65,14.88 arc(34.61,15.29) C22.1
UNNAMED_4_CAP_I131_N1: length 7.5
  TOP w0.635: RFIN3.1 36.83,30.23 arc(34.72,29.83) C21.1
UNNAMED_4_CAP_I145_N1: length 5
  TOP w0.635: C23.1 RFOUT3.1
UNNAMED_4_CAP_I145_N2: length 10.4
  TOP w0.305: R1.2 22.29,31.82
  TOP w0.635: C23.2 29.65,39.17 22.29,31.82
UNNAMED_4_CAP_I154_N1: length 7.6
  TOP w0.635: 6.48,45.11 RFOUT1.1 6.48,48.29 ; 6.48,45.11 6.48,44.96 ; 6.48,45.11 arc(6.87,43) C9.1
UNNAMED_4_CAP_I155_N1: length 7.5
  TOP w0.635: RFIN2.1 21.84,46.53 21.82,46.51 21.82,44.93 arc(21.41,42.89) C13.1
UNNAMED_4_CAP_I166_N1: length 2.2
  TOP w0.635: C28.2 14.35,36.83 13.84,36.83 C27.1
UNNAMED_4_CAP_I166_N2: length 11
  TOP w0.305: 13.36,25.31 U1.32 13.36,26.21
  TOP w0.381: 13.36,26.21 L1.2
  TOP w0.635: L1.2 13.02,27.77 arc(12.51,30.63) 12.34,33.53 arc(12.29,34.31) 12.16,35.09 12.07,35.43 arc(11.96,35.77) C27.2
UNNAMED_4_CAP_I167_N1: length 13.2
  TOP w0.254: 14.61,27.86 14.4,27.1 ; 14.4,27.1 15.14,27.89 ; 14.4,27.1 arc(14.37,26.96) 14.36,26.81 U1.30 14.36,25.31 ; 14.4,27.1 arc(14.53,27.46) 14.76,27.76
  TOP w0.635: 14.76,27.76 15.32,28.32 arc(15.72,28.92) 15.86,29.62 15.86,33.53 arc(15.98,34.84) C28.1
UNNAMED_4_CAP_I168_N1: length 2.1
  TOP w0.635: C30.1 28.13,22.11 arc(28.19,22.7) 28.09,23.28 C29.2
UNNAMED_4_CAP_I168_N2: length 10.4
  TOP w0.305: U1.18 18.26,21.6 ; L5.1 arc(20.73,21.5) 20.8,21.48
  TOP w0.635: 27.64,20.29 C30.2 arc(24.26,21.04) 20.8,21.48 arc(19.8,21.55) 18.8,21.59 arc(18.53,21.59) 18.26,21.6
UNNAMED_4_CAP_I169_N1: length 7.3
  TOP w0.635: C29.1 27.66,24.77 arc(24.7,24.08) L6.2 20.56,23.45
UNNAMED_4_CAP_I221_N1: length 1.8
  TOP w0.305: U1.21 18.39,23.14
  TOP w0.635: 18.39,23.14 arc(18.85,23.2) C3.1
UNNAMED_4_CAP_I233_N1: length 5.3
  TOP w0.305: VSW1_N.1 C6.1 R2.1
UNNAMED_4_CAP_I235_N1: length 6.3
  TOP w0.305: VSW1.1 16,14.76 R3.2
  BOTTOM w0.305: VSW1.1 C11.1
UNNAMED_4_CAP_I236_N1: length 8.5
  TOP w0.305: R4.2 17.78,15.9 19.08,14.6 20.73,14.6 VGAIN1.1
  BOTTOM w0.305: VGAIN1.1 C14.1
UNNAMED_4_CAP_I237_N1: length 10.9
  TOP w0.305: VGAIN2.1 23.37,16.54 R5.2
  BOTTOM w0.305: VGAIN2.1 C15.1
VPOS: length 2.4
  TOP w0.635: R7.2 v1(7.39,12.78) ; R6.1 v1(10.08,11.99)
VPOS1: length 9.9
  TOP w0.305: 12.57,18.67 L2.1 12.47,18.67
  TOP w0.508: VPOS1.1 R6.2 C2.2 C4.1 C7.1 12.57,18.67
VPOS2: length 17.9
  TOP w0.508: R7.1 4.98,15.85 VPOS2.1
  BOTTOM w0.305: L3.2 12.14,24.59 C16.1 11.81,24 11.81,21.97 C17.1 C20.2 ; 5,15.82 VPOS2.1
  BOTTOM w0.508: 5,15.82 7.39,18.21 10.39,18.21 11.68,19.51 C20.2

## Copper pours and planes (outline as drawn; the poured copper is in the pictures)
AGND on TOP: 0.51,0.41 0.51,50.29 30.28,50.29 42.04,38.53 42.04,0.41 ; 16 cut-outs
AGND on BOTTOM: 0.51,0.41 0.51,50.29 30.28,50.29 42.04,38.53 42.04,0.41 ; 1 cut-out
AGND on L2_GND: 41.91,0.41 0.51,0.41 0.51,50.29 30.15,50.29 41.91,38.53
AGND on L3_VCC: 0.51,0.41 0.51,50.29 30.28,50.29 42.04,38.53 42.04,0.41
VPOS on L3_VCC: 3.38,7.62 3.38,13.72 3.1,14 3.1,18.03 3.49,18.43 7.71,18.43 11.06,21.78 11.06,25.4 7.32,29.15 7.32,35.43 13.58,35.43 13.59,35.37 13.6,35.31 13.76,35.31 13.81,35.37 13.87,35.43 17.27,35.43 17.27,33.96 17.17,33.86 17.17,31.22 16.97,31.01 16.97,29.84 16.76,29.64 16.76,28.93 16.87,28.83 17.32,28.83 23.93,35.43 28.4,35.43 28.4,29.08 17.53,18.21 13.16,18.21 13,18.06 13,16.79 13.92,16.79 13.92,7.62 ; 21 cut-outs

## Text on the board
Ref Des/Silkscreen Bottom: ADL5246 | ADL5247 | SECONDARY SIDE
User.Comments: 08-      -04
Ref Des/Silkscreen Top: 038024 REV-B | 1 | 2 | 3 | A | 4 | 5 | B | 6 | C | 7 | D | 8 | E | 9 | 10 | F | G | ADL5247 EVAL BD Z | ADL5246 EVAL BD Z
PAGE_OUTLINE: B | UPDATE PER ECR# 045905 | 17APR14 | J.BEDROSIAN
DIMENSION: SOLDERPASTE_TOP/BOTTOM | ADD TO SUB-CLASS | USE ABOVE IN PASTE FILM FILES | TAKE CARE NOT TO LOSE VIAS & | ETCH WHEN MOVING COMPONENT | EDIT ETCH TO TIE TO CENTER PIN NET | SEE NOTE 15
User.12: ENIG (Electroless Nickel/Immersion Gold) | 100 MICRO INCHES NICKEL/ | 2-8 MICRO INCHES GOLD | 15.    DESIGNATED DRILL(S) TO BE FILLED WITH NON-CONDUCTIVE EPOXY AND | MADE CO-PLANAR ON THE PRIMARY SIDE. | 16.    BOARD MUST BE PALLETIZED AND SHIPPED INTACT. | AREAS WHERE THE SOLDER MASK IS OPEN | NO TABS ALLOWED ON
User.13: L2 GND | 08-      -07
User.14: L3 SPLIT PWR | 08-      -08
User.15: BUMP PRIMARY | 08-      -11
User.19: J.BEDROSIAN | 05MAR14 | UPDATE PER ECR# 045905 | B | 17APR14 | SECONDARY SIDE | 24355
User.24: FIGURE | SIZE | 12.0 | 63.0 | 115.0 | PLATED | NON-PLATED | FINISHED HOLES IN MILS | ALL UNITS ARE IN MILS | QTY | 594 | 11 | 3 | TOLERANCE/NOTES
